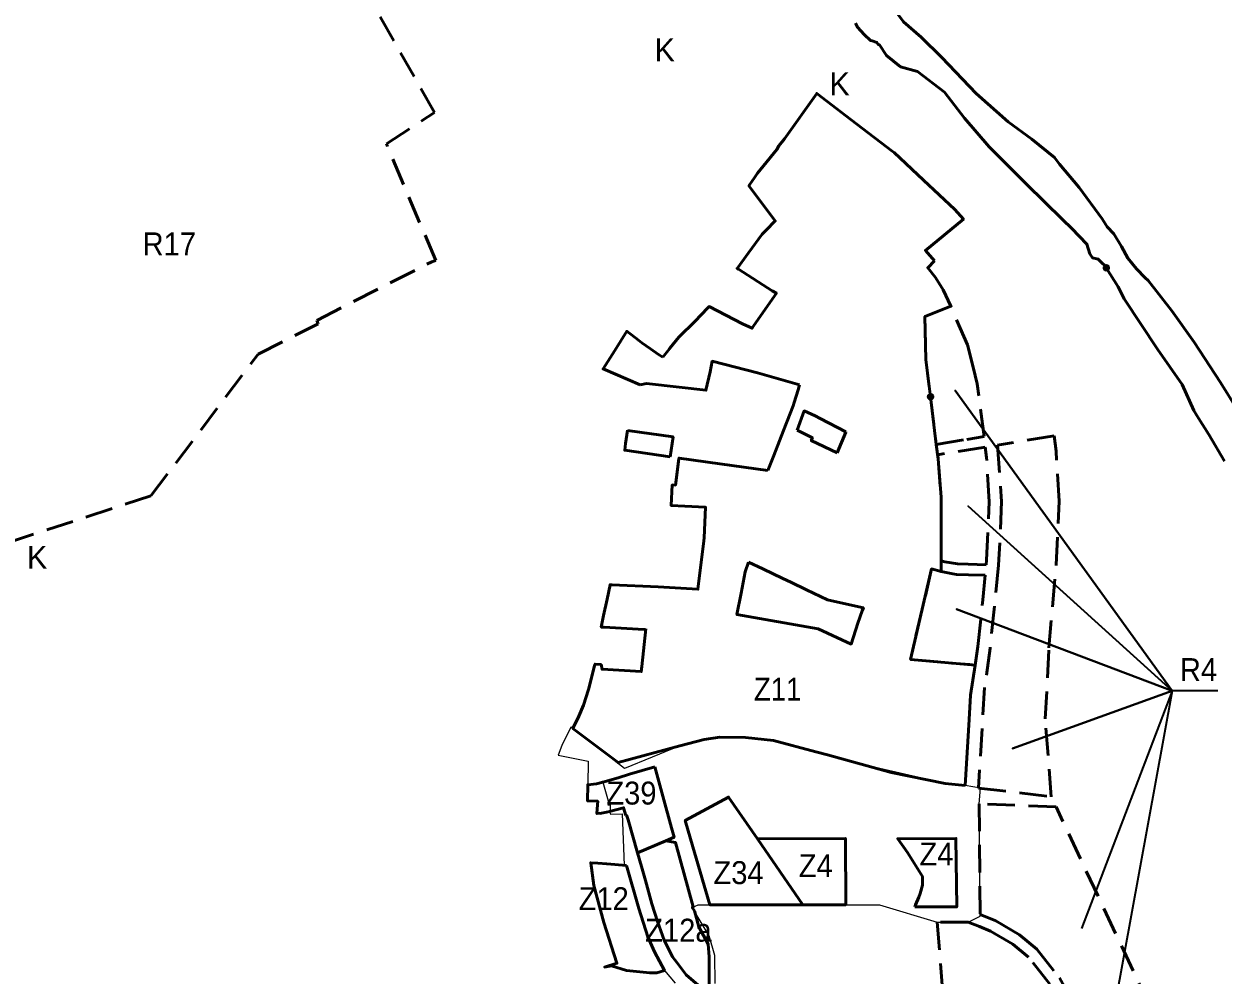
# Model space of a CAD drawing. Extents: x -650246 to -642674, y -1074280 to -1066767.
# Drawn here: x -646455 to -645200, y -1070188 to -1069193 of the extents above; entities that cross this region are included whole.
import ezdxf

# ---------------------------------------------------------------- set-up
doc = ezdxf.new("R2010")
doc.units = 0
doc.header["$LTSCALE"] = 9.6
doc.header["$PDMODE"] = 32
doc.header["$PDSIZE"] = 4.8
doc.linetypes.add('MEDIUM_DASHED', pattern=[4.5, 3, -1.5])
for name, color, linetype, lineweight in [('42', 7, 'Continuous', 25), ('44', 7, 'Continuous', 53), ('45', 7, 'Continuous', 53), ('46', 7, 'Continuous', 13), ('48', 7, 'Continuous', 13), ('61', 7, 'MEDIUM_DASHED', 53), ('62', 7, 'Continuous', 35)]:
    doc.layers.add(name, color=color, linetype=linetype, lineweight=lineweight)

msp = doc.modelspace()

# ---------------------------------------------------------------- linework, layer by layer
at = {"layer": '42'}
msp.add_lwpolyline([(-645731.3, -1070197.24), (-645731.94, -1070167.87), (-645737.63, -1070147.39), (-645755.4, -1070117.6), (-645749.28, -1070114.96), (-645737.075, -1070114.955), (-645637.56, -1070114.89), (-645559.63, -1070114.85), (-645499.129, -1070133.293), (-645466.862, -1070133.219), (-645454.051, -1070127.008), (-645455.073, -1070009.111), (-645453.852, -1069992.968), (-645469.701, -1069990.011), (-645490.814, -1069988.074), (-645601.753, -1069962.317), (-645614.072, -1069957.797), (-645625.979, -1069954.92), (-645670.325, -1069943.002), (-645699.889, -1069939.714), (-645726.542, -1069939.398), (-645742.967, -1069941.862), (-645768.424, -1069948.431), (-645826.321, -1069972.247), (-645880.431, -1069930.3), (-645882.381, -1069928.788), (-645892.09, -1069947.98), (-645895.66, -1069958.42), (-645864.48, -1069964.53), (-645864.77, -1069989.26), (-645855.54, -1069988.24), (-645849.1, -1069986.42), (-645842.8, -1070008.59), (-645843.74, -1070010.25), (-645841.43, -1070010.21), (-645841.21, -1070017.31), (-645841.89, -1070017.42), (-645841.075, -1070020.163), (-645828.963, -1070019.709), (-645826.615, -1070073.495), (-645824.28, -1070073.67), (-645811.48, -1070118.65), (-645801.99, -1070148.51), (-645795.07, -1070164.26), (-645784.51, -1070183.77), (-645773.48, -1070197.1)], dxfattribs=at)
at = {"layer": '44'}
for points in [[(-645184.88, -1069596.58), (-645202.56, -1069568.23), (-645230.1, -1069525.98), (-645253.4, -1069493.06), (-645278.31, -1069461.33), (-645281.4, -1069458.4), (-645290.5, -1069449.03), (-645299.61, -1069437.97), (-645306.16, -1069425.55), (-645314.14, -1069412.54), (-645321.1, -1069405.21), (-645326.59, -1069396.64), (-645350.63, -1069363.98), (-645371.12, -1069339.47), (-645376.38, -1069332.65), (-645400.07, -1069313.32), (-645424.8, -1069295.24), (-645458.45, -1069265.56), (-645494.13, -1069227.63), (-645515.89, -1069206.66), (-645534.25, -1069190.56), (-645543.43, -1069178.39)], [(-645584.73, -1069191.88), (-645582.63, -1069195.88), (-645575.58, -1069203.57), (-645568.9, -1069209.87), (-645567.07, -1069210.45), (-645562.17, -1069212.02), (-645560.72, -1069214.25), (-645559.33, -1069214.54), (-645552.2, -1069225.59), (-645537.44, -1069237.41), (-645519.59, -1069242.38), (-645491.63, -1069264.25), (-645470.44, -1069291.24), (-645444.62, -1069321.35), (-645405.7, -1069360.27), (-645368.13, -1069397.37), (-645358.04, -1069406.84), (-645342.49, -1069423.06), (-645339.31, -1069433.27), (-645336.66, -1069437.47), (-645330.57, -1069438.89), (-645327.2, -1069442.53), (-645323.36, -1069445.79), (-645322.13, -1069447.96)], [(-645322.13, -1069447.96), (-645309.62, -1069467.79), (-645303.57, -1069480.49), (-645268.57, -1069533.23), (-645242.75, -1069570.26), (-645230.42, -1069597.39), (-645227.27, -1069602.68), (-645225.7, -1069605.32), (-645214.76, -1069622.37), (-645198.41, -1069650.49)]]:
    msp.add_lwpolyline(points, dxfattribs=at)
msp.add_point((-645322.13, -1069447.96), dxfattribs=at)
at = {"layer": '45'}
msp.add_line((-645726.542, -1069939.398), (-645742.967, -1069941.862), dxfattribs=at)
msp.add_line((-645726.542, -1069939.398), (-645742.967, -1069941.862), dxfattribs=at)
for points in [[(-645668.722, -1069398.75), (-645696.19, -1069362.01), (-645692.38, -1069356.67), (-645690.81, -1069354.28), (-645687.22, -1069349), (-645680.8, -1069341.08), (-645667, -1069324.06), (-645664.89, -1069320.2), (-645658.9, -1069312.83), (-645625.11, -1069265.42), (-645604.114, -1069281.49), (-645594.94, -1069288.511)], [(-645668.722, -1069398.75), (-645696.19, -1069362.01), (-645692.38, -1069356.67), (-645690.81, -1069354.28), (-645687.22, -1069349), (-645680.8, -1069341.08), (-645667, -1069324.06), (-645664.89, -1069320.2), (-645658.9, -1069312.83), (-645625.11, -1069265.42), (-645604.114, -1069281.49), (-645594.94, -1069288.511)], [(-645594.94, -1069288.511), (-645583.13, -1069297.55), (-645546.19, -1069325.81), (-645544.26, -1069327.35), (-645513.41, -1069356.18), (-645480.72, -1069386.96), (-645471.738, -1069397.026), (-645511.464, -1069429.794), (-645501.878, -1069440.838)], [(-645594.94, -1069288.511), (-645583.13, -1069297.55), (-645546.19, -1069325.81), (-645544.26, -1069327.35), (-645513.41, -1069356.18), (-645480.72, -1069386.96), (-645471.738, -1069397.026), (-645511.464, -1069429.794), (-645501.878, -1069440.838)], [(-645707.04, -1069449.546), (-645708.48, -1069448.63), (-645696.45, -1069432.21), (-645682.28, -1069412.88), (-645678.06, -1069408.54), (-645668.61, -1069398.9), (-645668.722, -1069398.75)], [(-645707.04, -1069449.546), (-645708.48, -1069448.63), (-645696.45, -1069432.21), (-645682.28, -1069412.88), (-645678.06, -1069408.54), (-645668.61, -1069398.9), (-645668.722, -1069398.75)], [(-645786.388, -1069541.673), (-645779.376, -1069532.962), (-645778.754, -1069532.198), (-645769.369, -1069520.672), (-645768.995, -1069520.305), (-645752.715, -1069504.328), (-645738.986, -1069489.868), (-645737.897, -1069488.534), (-645702.82, -1069506.64), (-645692.87, -1069511.229), (-645690.84, -1069508.32), (-645667.31, -1069474.6), (-645671.75, -1069471.99), (-645707.04, -1069449.546)], [(-645786.388, -1069541.673), (-645779.376, -1069532.962), (-645778.754, -1069532.198), (-645769.369, -1069520.672), (-645768.995, -1069520.305), (-645752.715, -1069504.328), (-645738.986, -1069489.868), (-645737.897, -1069488.534), (-645702.82, -1069506.64), (-645692.87, -1069511.229), (-645690.84, -1069508.32), (-645667.31, -1069474.6), (-645671.75, -1069471.99), (-645707.04, -1069449.546)], [(-645501.878, -1069440.838), (-645508.994, -1069447.955), (-645501, -1069458), (-645493, -1069471), (-645484.783, -1069488.256), (-645512, -1069499), (-645511, -1069544), (-645506, -1069583)], [(-645501.878, -1069440.838), (-645508.994, -1069447.955), (-645501, -1069458), (-645493, -1069471), (-645484.783, -1069488.256), (-645512, -1069499), (-645511, -1069544), (-645506, -1069583)], [(-645836.44, -1069534.5), (-645824.05, -1069514.34), (-645811.75, -1069523.81), (-645808.1, -1069526.61), (-645799.07, -1069532.8), (-645790.62, -1069538.59), (-645786.388, -1069541.673)], [(-645836.44, -1069534.5), (-645824.05, -1069514.34), (-645811.75, -1069523.81), (-645808.1, -1069526.61), (-645799.07, -1069532.8), (-645790.62, -1069538.59), (-645786.388, -1069541.673)], [(-645810.08, -1069570.39), (-645848.78, -1069553.91), (-645836.44, -1069534.5)], [(-645810.08, -1069570.39), (-645848.78, -1069553.91), (-645836.44, -1069534.5)], [(-645643.16, -1069570.6), (-645687.29, -1069558.04), (-645734.5, -1069545.89), (-645736.8, -1069556.91), (-645741.14, -1069576.19), (-645769.04, -1069573), (-645803.513, -1069569.263), (-645810.08, -1069570.39)], [(-645643.16, -1069570.6), (-645687.29, -1069558.04), (-645734.5, -1069545.89), (-645736.8, -1069556.91), (-645741.14, -1069576.19), (-645769.04, -1069573), (-645803.513, -1069569.263), (-645810.08, -1069570.39)], [(-645676.34, -1069660.28), (-645670.23, -1069644.67), (-645664.19, -1069629.24), (-645657.52, -1069612.2), (-645656.15, -1069608.71), (-645649.91, -1069592.39), (-645648.68, -1069589.06), (-645644.56, -1069575.61), (-645643.16, -1069570.6)], [(-645676.34, -1069660.28), (-645670.23, -1069644.67), (-645664.19, -1069629.24), (-645657.52, -1069612.2), (-645656.15, -1069608.71), (-645649.91, -1069592.39), (-645648.68, -1069589.06), (-645644.56, -1069575.61), (-645643.16, -1069570.6)], [(-645506, -1069583), (-645500.137, -1069632.833), (-645500.137, -1069632.833)], [(-645506, -1069583), (-645500.137, -1069632.833), (-645500.137, -1069632.833)], [(-645594.58, -1069619.56), (-645621.56, -1069605.68), (-645626.95, -1069602.91), (-645638.203, -1069597.8), (-645645.715, -1069618.085)], [(-645594.58, -1069619.56), (-645621.56, -1069605.68), (-645626.95, -1069602.91), (-645638.203, -1069597.8), (-645645.715, -1069618.085)], [(-645594.58, -1069619.56), (-645621.56, -1069605.68), (-645626.95, -1069602.91), (-645638.203, -1069597.8), (-645645.715, -1069618.085)], [(-645594.58, -1069619.56), (-645621.56, -1069605.68), (-645626.95, -1069602.91), (-645638.203, -1069597.8), (-645645.715, -1069618.085)], [(-645823.082, -1069618.279), (-645823.13, -1069618.452), (-645825.295, -1069632.053), (-645826.133, -1069638.843), (-645826.151, -1069639.057), (-645778.45, -1069645.92)], [(-645823.082, -1069618.279), (-645823.13, -1069618.452), (-645825.295, -1069632.053), (-645826.133, -1069638.843), (-645826.151, -1069639.057), (-645778.45, -1069645.92)], [(-645778.45, -1069645.92), (-645775.46, -1069625.13), (-645823.082, -1069618.279)], [(-645778.45, -1069645.92), (-645775.46, -1069625.13), (-645823.082, -1069618.279)], [(-645645.715, -1069618.085), (-645629.78, -1069626.03), (-645630.93, -1069628.84), (-645603.7, -1069641.75)], [(-645645.715, -1069618.085), (-645629.78, -1069626.03), (-645630.93, -1069628.84), (-645603.7, -1069641.75)], [(-645645.715, -1069618.085), (-645629.78, -1069626.03), (-645630.93, -1069628.84), (-645603.7, -1069641.75)], [(-645645.715, -1069618.085), (-645629.78, -1069626.03), (-645630.93, -1069628.84), (-645603.7, -1069641.75)], [(-645603.7, -1069641.75), (-645594.818, -1069620.139), (-645594.58, -1069619.56)], [(-645603.7, -1069641.75), (-645594.818, -1069620.139), (-645594.58, -1069619.56)], [(-645603.7, -1069641.75), (-645594.818, -1069620.139), (-645594.58, -1069619.56)], [(-645603.7, -1069641.75), (-645594.818, -1069620.139), (-645594.58, -1069619.56)], [(-645500.137, -1069632.833), (-645498, -1069648), (-645495, -1069688), (-645495, -1069744), (-645495, -1069766), (-645504.976, -1069763.332), (-645527, -1069858), (-645459.312, -1069864.01), (-645464.288, -1069895.362), (-645465.756, -1069921.035), (-645469.701, -1069990.011)], [(-645500.137, -1069632.833), (-645498, -1069648), (-645495, -1069688), (-645495, -1069744), (-645495, -1069766), (-645504.976, -1069763.332), (-645527, -1069858), (-645459.312, -1069864.01), (-645464.288, -1069895.362), (-645465.756, -1069921.035), (-645469.701, -1069990.011)], [(-645839.721, -1069780.247), (-645839.658, -1069779.835), (-645791.2, -1069781.92), (-645749.48, -1069784.61), (-645743.36, -1069733.7), (-645743.01, -1069730.72), (-645741.43, -1069698.68), (-645763.24, -1069697.58), (-645777.62, -1069696.85), (-645776.45, -1069675.26), (-645773.02, -1069675.47), (-645769.36, -1069648), (-645769.264, -1069647.213), (-645726.57, -1069653.22), (-645676.34, -1069660.28)], [(-645839.721, -1069780.247), (-645839.658, -1069779.835), (-645791.2, -1069781.92), (-645749.48, -1069784.61), (-645743.36, -1069733.7), (-645743.01, -1069730.72), (-645741.43, -1069698.68), (-645763.24, -1069697.58), (-645777.62, -1069696.85), (-645776.45, -1069675.26), (-645773.02, -1069675.47), (-645769.36, -1069648), (-645769.264, -1069647.213), (-645726.57, -1069653.22), (-645676.34, -1069660.28)], [(-645696.517, -1069756.039), (-645700.028, -1069766.286), (-645704.355, -1069788.786)], [(-645696.517, -1069756.039), (-645700.028, -1069766.286), (-645704.355, -1069788.786)], [(-645660.57, -1069773.31), (-645681.76, -1069763.13), (-645696.517, -1069756.039)], [(-645660.57, -1069773.31), (-645681.76, -1069763.13), (-645696.517, -1069756.039)], [(-645613.84, -1069795.78), (-645635.79, -1069785.23), (-645652.378, -1069777.251), (-645660.57, -1069773.31)], [(-645613.84, -1069795.78), (-645635.79, -1069785.23), (-645652.378, -1069777.251), (-645660.57, -1069773.31)], [(-645804.185, -1069825.84), (-645804.28, -1069826.76), (-645812.18, -1069826.3), (-645847.62, -1069824.26), (-645850.63, -1069824.09), (-645848.35, -1069812.09), (-645844.57, -1069795.07), (-645841.41, -1069779.76), (-645839.658, -1069779.835), (-645839.721, -1069780.247)], [(-645804.185, -1069825.84), (-645804.28, -1069826.76), (-645812.18, -1069826.3), (-645847.62, -1069824.26), (-645850.63, -1069824.09), (-645848.35, -1069812.09), (-645844.57, -1069795.07), (-645841.41, -1069779.76), (-645839.658, -1069779.835), (-645839.721, -1069780.247)], [(-645704.355, -1069788.786), (-645708.633, -1069811.027), (-645623.75, -1069825.97)], [(-645704.355, -1069788.786), (-645708.633, -1069811.027), (-645623.75, -1069825.97)], [(-645623.75, -1069825.97), (-645589.23, -1069841.89), (-645582.31, -1069820.05), (-645577.52, -1069807.26), (-645576.34, -1069804.13), (-645578.134, -1069803.731), (-645613.84, -1069795.78)], [(-645623.75, -1069825.97), (-645589.23, -1069841.89), (-645582.31, -1069820.05), (-645577.52, -1069807.26), (-645576.34, -1069804.13), (-645578.134, -1069803.731), (-645613.84, -1069795.78)], [(-645742.967, -1069941.862), (-645768.424, -1069948.431), (-645833, -1069966), (-645880.431, -1069930.3), (-645874.219, -1069917.496), (-645869.262, -1069905.935), (-645863.95, -1069889.468), (-645857.289, -1069863.338), (-645857.204, -1069862.954), (-645850.92, -1069863.41), (-645849.79, -1069868.4), (-645808.84, -1069870.75), (-645808.28, -1069865.39), (-645804.185, -1069825.84)], [(-645742.967, -1069941.862), (-645768.424, -1069948.431), (-645833, -1069966), (-645880.431, -1069930.3), (-645874.219, -1069917.496), (-645869.262, -1069905.935), (-645863.95, -1069889.468), (-645857.289, -1069863.338), (-645857.204, -1069862.954), (-645850.92, -1069863.41), (-645849.79, -1069868.4), (-645808.84, -1069870.75), (-645808.28, -1069865.39), (-645804.185, -1069825.84)], [(-645469.701, -1069990.011), (-645490.814, -1069988.074), (-645547.4, -1069976.382), (-645614.072, -1069957.797), (-645625.979, -1069954.92), (-645670.325, -1069943.002), (-645699.889, -1069939.714), (-645726.542, -1069939.398)], [(-645469.701, -1069990.011), (-645490.814, -1069988.074), (-645547.4, -1069976.382), (-645614.072, -1069957.797), (-645625.979, -1069954.92), (-645670.325, -1069943.002), (-645699.889, -1069939.714), (-645726.542, -1069939.398)], [(-645794.679, -1069970.596), (-645821, -1069978), (-645833, -1069982)], [(-645794.679, -1069970.596), (-645821, -1069978), (-645833, -1069982)], [(-645777.143, -1070034.287), (-645786.238, -1070001.251), (-645794.679, -1069970.596)], [(-645777.143, -1070034.287), (-645786.238, -1070001.251), (-645794.679, -1069970.596)], [(-645833, -1069982), (-645849.1, -1069986.42), (-645855.54, -1069988.24), (-645864.77, -1069989.26), (-645864.97, -1070006.16), (-645854.42, -1070006.47), (-645854.65, -1070010.44), (-645855.17, -1070019.44), (-645852.36, -1070019.01), (-645852.33, -1070019.2), (-645845.37, -1070018.12), (-645845.14, -1070018.08), (-645845.17, -1070017.91), (-645841.89, -1070017.42), (-645827.365, -1070013.291), (-645825.08, -1070021.52)], [(-645833, -1069982), (-645849.1, -1069986.42), (-645855.54, -1069988.24), (-645864.77, -1069989.26), (-645864.97, -1070006.16), (-645854.42, -1070006.47), (-645854.65, -1070010.44), (-645855.17, -1070019.44), (-645852.36, -1070019.01), (-645852.33, -1070019.2), (-645845.37, -1070018.12), (-645845.14, -1070018.08), (-645845.17, -1070017.91), (-645841.89, -1070017.42), (-645827.365, -1070013.291), (-645825.08, -1070021.52)], [(-645825.08, -1070021.52), (-645823.76, -1070021.67), (-645822.549, -1070025.948), (-645812.76, -1070060.53), (-645783.063, -1070047.855), (-645774.423, -1070044.167), (-645777.143, -1070034.287)], [(-645825.08, -1070021.52), (-645823.76, -1070021.67), (-645822.549, -1070025.948), (-645812.76, -1070060.53), (-645783.063, -1070047.855), (-645774.423, -1070044.167), (-645777.143, -1070034.287)], [(-645753.182, -1070121.317), (-645755.4, -1070117.6), (-645754.333, -1070117.14), (-645772.853, -1070049.868), (-645783.063, -1070047.855), (-645812.76, -1070060.53), (-645808.721, -1070074.795), (-645804.52, -1070089.63), (-645797.66, -1070113.88), (-645791.72, -1070132.59)], [(-645824.28, -1070073.67), (-645845.01, -1070072.12), (-645854.25, -1070071.4), (-645861.74, -1070070.95), (-645858.53, -1070094.64), (-645847.88, -1070133.4)], [(-645795.07, -1070164.26), (-645801.99, -1070148.51), (-645811.48, -1070118.65), (-645824.28, -1070073.67)], [(-645737.756, -1070204.389), (-645737.624, -1070169.544), (-645738.79, -1070156.281), (-645748.62, -1070137.889), (-645753.182, -1070121.317)], [(-645847.88, -1070133.4), (-645834.31, -1070176.15), (-645847.2, -1070180.14), (-645839.82, -1070178.94), (-645824.12, -1070183.63), (-645799.91, -1070186.32), (-645792.37, -1070186.01), (-645784.51, -1070183.77), (-645795.07, -1070164.26)], [(-645791.72, -1070132.59), (-645784.83, -1070151.9), (-645776.26, -1070169.44), (-645771.246, -1070175.64)], [(-645771.246, -1070175.64), (-645761.78, -1070188.29), (-645746.73, -1070201.04), (-645739.12, -1070205.9), (-645737.756, -1070204.389)]]:
    msp.add_lwpolyline(points, dxfattribs=at)
for points in [[(-645639.638, -1070114.895), (-645687.31, -1070045.724), (-645717.36, -1070002.12), (-645762.868, -1070026.606), (-645757.215, -1070045.97), (-645737.075, -1070114.955)], [(-645639.638, -1070114.895), (-645687.31, -1070045.724), (-645717.36, -1070002.12), (-645762.868, -1070026.606), (-645757.215, -1070045.97), (-645737.075, -1070114.955)], [(-645639.638, -1070114.895), (-645594.733, -1070114.868), (-645595.2, -1070045.403), (-645687.31, -1070045.724)], [(-645639.638, -1070114.895), (-645594.733, -1070114.868), (-645595.2, -1070045.403), (-645687.31, -1070045.724)], [(-645522.587, -1070116.952), (-645478.664, -1070117.114), (-645479.429, -1070045.409), (-645540.433, -1070045.752), (-645530.3, -1070060.08), (-645514.49, -1070085.4), (-645514.56, -1070090.91), (-645514.61, -1070094.35), (-645517.02, -1070103.08), (-645518.35, -1070106.87), (-645521.73, -1070114.83)], [(-645522.587, -1070116.952), (-645478.664, -1070117.114), (-645479.429, -1070045.409), (-645540.433, -1070045.752), (-645530.3, -1070060.08), (-645514.49, -1070085.4), (-645514.56, -1070090.91), (-645514.61, -1070094.35), (-645517.02, -1070103.08), (-645518.35, -1070106.87), (-645521.73, -1070114.83)]]:
    msp.add_lwpolyline(points, close=True, dxfattribs=at)
msp.add_point((-645506, -1069583), dxfattribs=at)
at = {"layer": '61'}
for points in [[(-646583.457, -1069759.191), (-646554.262, -1069762.602), (-646321.973, -1069686.855), (-646209.9, -1069538.5), (-646146.8, -1069506.6), (-646148.5, -1069503), (-646028.16, -1069441.58), (-646023.96, -1069440.34), (-646075.49, -1069318.19), (-646025.14, -1069285.394), (-646153.307, -1069059.947)], [(-645381.213, -1070198.011), (-645403.604, -1070169.942), (-645420.081, -1070156.179), (-645443.191, -1070142.473), (-645454.881, -1070137.836), (-645466.862, -1070133.22), (-645499.142, -1070133.293), (-645493.76, -1070199.15)]]:
    msp.add_lwpolyline(points, dxfattribs=at)
for points in [[(-645506, -1069583), (-645500.137, -1069632.833), (-645468, -1069627.622), (-645450.05, -1069624.711), (-645457.223, -1069569.632), (-645461.32, -1069552.039), (-645467.477, -1069528.79), (-645484.783, -1069488.256), (-645512, -1069499), (-645511, -1069544)], [(-645374.642, -1069640.059), (-645376.605, -1069623.944), (-645435.877, -1069633.555), (-645431.642, -1069692.811), (-645434.826, -1069759.235), (-645443.679, -1069846.142), (-645449.445, -1069887.328), (-645455.84, -1069992.731), (-645379.881, -1070001.766), (-645385.95, -1069920.347), (-645382.14, -1069845.883), (-645378.587, -1069802.788), (-645374.542, -1069758.923), (-645371.563, -1069692.39)], [(-645495, -1069688), (-645495, -1069744), (-645495, -1069754.815), (-645491, -1069756), (-645478, -1069758), (-645466.517, -1069758.328), (-645447.852, -1069758.862), (-645447.398, -1069753.935), (-645444.664, -1069692.902), (-645447.387, -1069646.623), (-645448.725, -1069635.639), (-645498.61, -1069643.729), (-645498, -1069648)], [(-645504.976, -1069763.332), (-645527, -1069858), (-645464.93, -1069863.477), (-645459.312, -1069864.01), (-645456.586, -1069844.534), (-645451.227, -1069795.473), (-645448.864, -1069769.837), (-645466.353, -1069769.337), (-645478.997, -1069768.976), (-645482.753, -1069768.26), (-645495, -1069766)], [(-645374.685, -1070012.289), (-645455.073, -1070009.111), (-645454.066, -1070125.249), (-645437.885, -1070131.669), (-645413.129, -1070146.351), (-645394.98, -1070161.51), (-645371.209, -1070191.309), (-645336.176, -1070254.367), (-645308.702, -1070311.792), (-645289.153, -1070360.302), (-645219.594, -1070347.682), (-645238.856, -1070303.185), (-645246.433, -1070284.382), (-645275.729, -1070223.153)]]:
    msp.add_lwpolyline(points, close=True, dxfattribs=at)
at = {"layer": '62'}
msp.add_line((-645253.165, -1069890.903), (-645338.143, -1070356.741), dxfattribs=at)
msp.add_lwpolyline([(-645205.454, -1069890.903), (-645253.165, -1069890.903), (-645480.406, -1069576.285), (-645253.165, -1069890.903), (-645466.774, -1069697.69), (-645253.165, -1069890.903), (-645479.043, -1069805.455), (-645253.165, -1069890.903), (-645420.426, -1069951.415), (-645253.165, -1069890.903), (-645348.178, -1070139.662)], dxfattribs=at)

# ---------------------------------------------------------------- texts
at = {"layer": '46'}
for s, width, p in [('Z11', 0.9, (-645690.933, -1069901.172)), ('Z11', 0.9, (-645690.933, -1069901.172)), ('Z39', 0.95, (-645845.387, -1070009.975)), ('Z39', 0.95, (-645845.387, -1070009.975)), ('Z4', 0.95, (-645517.623, -1070073.78)), ('Z4', 0.95, (-645517.623, -1070073.78)), ('Z4', 0.95, (-645644.02, -1070085.964)), ('Z4', 0.95, (-645644.02, -1070085.964)), ('Z34', 0.95, (-645733.26, -1070093.266)), ('Z34', 0.95, (-645733.26, -1070093.266)), ('Z12', 0.95, (-645874.409, -1070120.563)), ('Z12a', 0.95, (-645804.738, -1070153.542))]:
    msp.add_text(s, height=24, dxfattribs=dict(at, width=width)).set_placement(p)
at = {"layer": '48'}
for p in [(-645795.003, -1069231.861), (-645795.003, -1069231.861), (-645611.977, -1069267.447), (-646451.743, -1069763.13), (-646451.743, -1069763.13)]:
    msp.add_text('K', height=24, dxfattribs=at).set_placement(p)
at = {"layer": '62', "width": 0.95}
for s, p in [('R17', (-646330.736, -1069434.917)), ('R4', (-645245.139, -1069880.683))]:
    msp.add_text(s, height=24, dxfattribs=at).set_placement(p)

doc.saveas('drawing.dxf')
